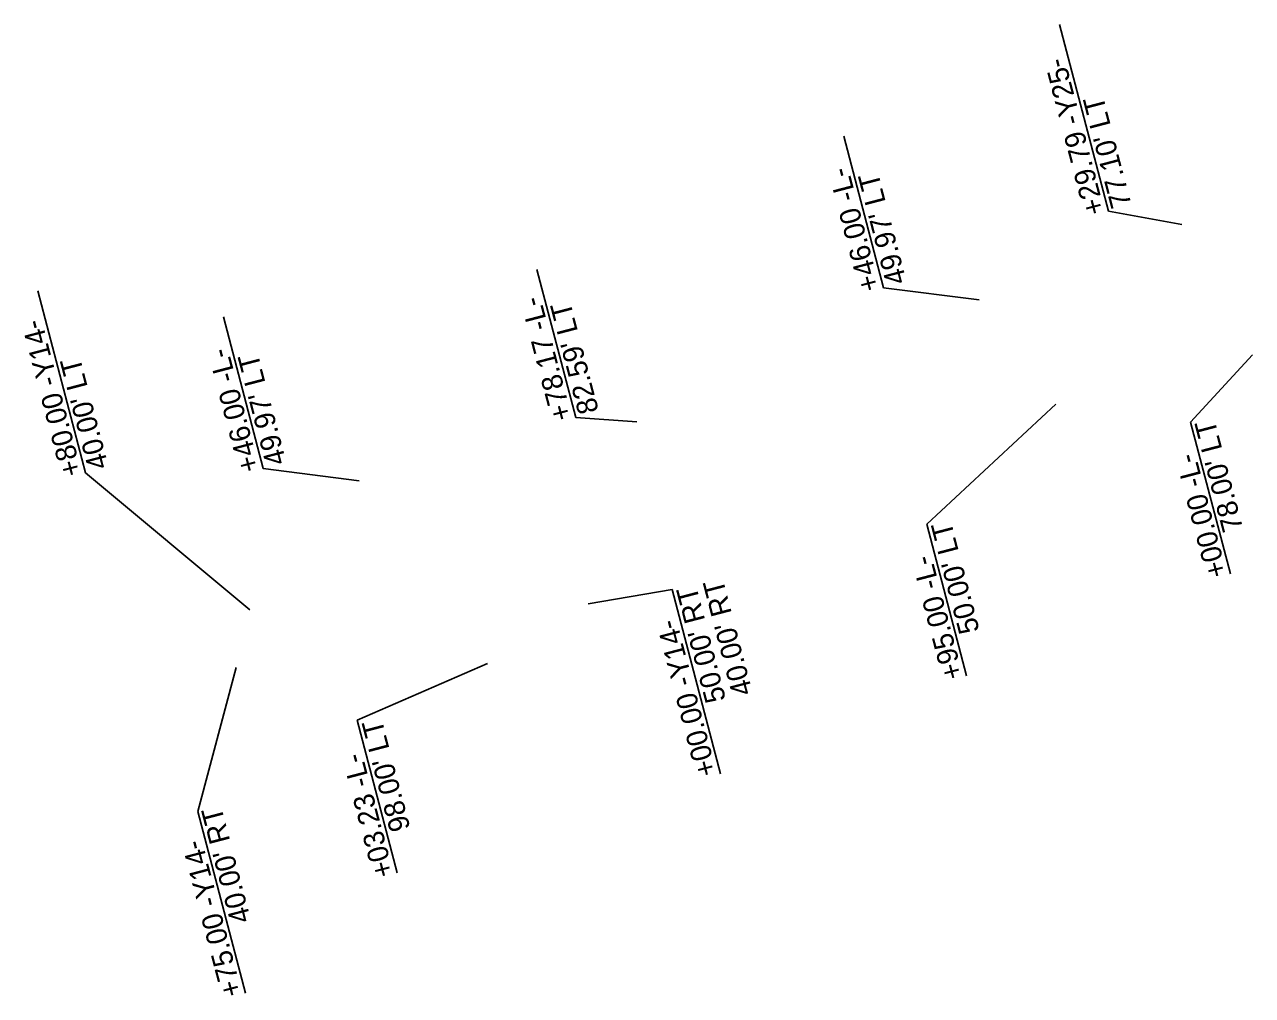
# Model space of a CAD drawing. Extents: x 1366833 to 1368739, y 877580 to 880469.
# Drawn here: x 1368561.2 to 1368739.4, y 877580.1 to 877721 of the extents above; entities that cross this region are included whole.
import ezdxf

# ---------------------------------------------------------------- set-up
doc = ezdxf.new("R2010")
doc.units = 0
for name, color, linetype in [('Exist Hydro Jurisdictional Stream or Body of Water', 7, 'Continuous'), ('Exist Structure Major Deck Tunnel Box Culvert', 7, 'Continuous'), ('Prop Horizontal Alignment Station Label', 7, 'Continuous'), ('Scratch_Level_0', 7, 'Continuous'), ('Sheet Clip Boundary CELL', 7, 'Continuous')]:
    doc.layers.add(name, color=color, linetype=linetype)

msp = doc.modelspace()

# ---------------------------------------------------------------- linework, layer by layer
at = {"layer": 'Exist Hydro Jurisdictional Stream or Body of Water'}
for p, q in [((1368590.03, 877678.58), (1368595.8, 877656.57)), ((1368615.25, 877597.92), (1368609.44, 877620.07))]:
    msp.add_line(p, q, dxfattribs=at)
for points in [[(1368595.8, 877656.57), (1368609.71, 877654.79)], [(1368609.44, 877620.07), (1368628.36, 877628.31)]]:
    msp.add_lwpolyline(points, dxfattribs=at)
at = {"layer": 'Exist Structure Major Deck Tunnel Box Culvert'}
for p, q in [((1368563.08, 877682.34), (1368569.99, 877655.97)), ((1368586.32, 877606.84), (1368593.23, 877580.47))]:
    msp.add_line(p, q, dxfattribs=at)
for points in [[(1368569.99, 877655.97), (1368593.88, 877636.06)], [(1368586.32, 877606.84), (1368591.9, 877627.7)]]:
    msp.add_lwpolyline(points, dxfattribs=at)
at = {"layer": 'Prop Horizontal Alignment Station Label'}
for p, q in [((1368711.38, 877720.98), (1368718.47, 877693.91)), ((1368730.41, 877663.3), (1368736.18, 877641.29))]:
    msp.add_line(p, q, dxfattribs=at)
for points in [[(1368718.47, 877693.91), (1368729.13, 877691.99)], [(1368730.41, 877663.3), (1368739.38, 877673.06)]]:
    msp.add_lwpolyline(points, dxfattribs=at)
at = {"layer": 'Scratch_Level_0'}
for p, q in [((1368635.54, 877685.43), (1368641.17, 877663.97)), ((1368655.18, 877639.02), (1368662.19, 877612.27))]:
    msp.add_line(p, q, dxfattribs=at)
for points in [[(1368641.17, 877663.97), (1368650.03, 877663.34)], [(1368655.18, 877639.02), (1368642.98, 877636.94)]]:
    msp.add_lwpolyline(points, dxfattribs=at)
at = {"layer": 'Sheet Clip Boundary CELL'}
for p, q in [((1368680.06, 877704.8), (1368685.83, 877682.79)), ((1368692.13, 877648.5), (1368697.9, 877626.49))]:
    msp.add_line(p, q, dxfattribs=at)
for points in [[(1368685.83, 877682.79), (1368699.74, 877681.02)], [(1368692.13, 877648.5), (1368710.85, 877665.91)]]:
    msp.add_lwpolyline(points, dxfattribs=at)

# ---------------------------------------------------------------- texts
at = {"layer": 'Exist Hydro Jurisdictional Stream or Body of Water'}
for s, p in [('+46.00 -L-', (1368595.31, 877656.44)), ("49.97' LT", (1368599.18, 877657.46)), ("98.00' LT", (1368617.18, 877604.35)), ('+03.23 -L-', (1368614.79, 877597.67))]:
    msp.add_text(s, height=3, rotation=104.6851, dxfattribs=at).set_placement(p)
at = {"layer": 'Exist Structure Major Deck Tunnel Box Culvert'}
for s, p in [('+80.00 -Y14-', (1368569.51, 877655.85)), ("40.00' LT", (1368573.38, 877656.86)), ("40.00' RT", (1368594.05, 877591.03)), ('+75.00 -Y14-', (1368592.78, 877580.35))]:
    msp.add_text(s, height=3, rotation=104.6851, dxfattribs=at).set_placement(p)
at = {"layer": 'Prop Horizontal Alignment Station Label'}
for s, p in [('+29.79 -Y25-', (1368717.99, 877693.79)), ("77.10' LT", (1368721.86, 877694.8)), ("78.00' LT", (1368738.05, 877647.83)), ('+00.00 -L-', (1368735.73, 877641.17))]:
    msp.add_text(s, height=3, rotation=104.6851, dxfattribs=at).set_placement(p)
at = {"layer": 'Scratch_Level_0'}
for s, p in [('+78.17 -L-', (1368640.66, 877663.92)), ("82.59' LT", (1368644.53, 877664.93)), ("40.00' RT", (1368666.86, 877624.04)), ("50.00' RT", (1368662.99, 877623.03)), ('+00.00 -Y14-', (1368661.66, 877612.33))]:
    msp.add_text(s, height=3, rotation=104.6851, dxfattribs=at).set_placement(p)
at = {"layer": 'Sheet Clip Boundary CELL'}
for s, p in [('+46.00 -L-', (1368685.34, 877682.67)), ("49.97' LT", (1368689.21, 877683.68)), ("50.00' LT", (1368699.8, 877633.04)), ('+95.00 -L-', (1368697.42, 877626.37))]:
    msp.add_text(s, height=3, rotation=104.6851, dxfattribs=at).set_placement(p)

doc.saveas('drawing.dxf')
